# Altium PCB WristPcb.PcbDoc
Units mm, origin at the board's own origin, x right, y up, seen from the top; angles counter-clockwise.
Board outline 152.4 x 101.6 mm, 2 copper layers (Top Layer, Bottom Layer); 4 components, 45 nets, 73 pads, 2 vias.
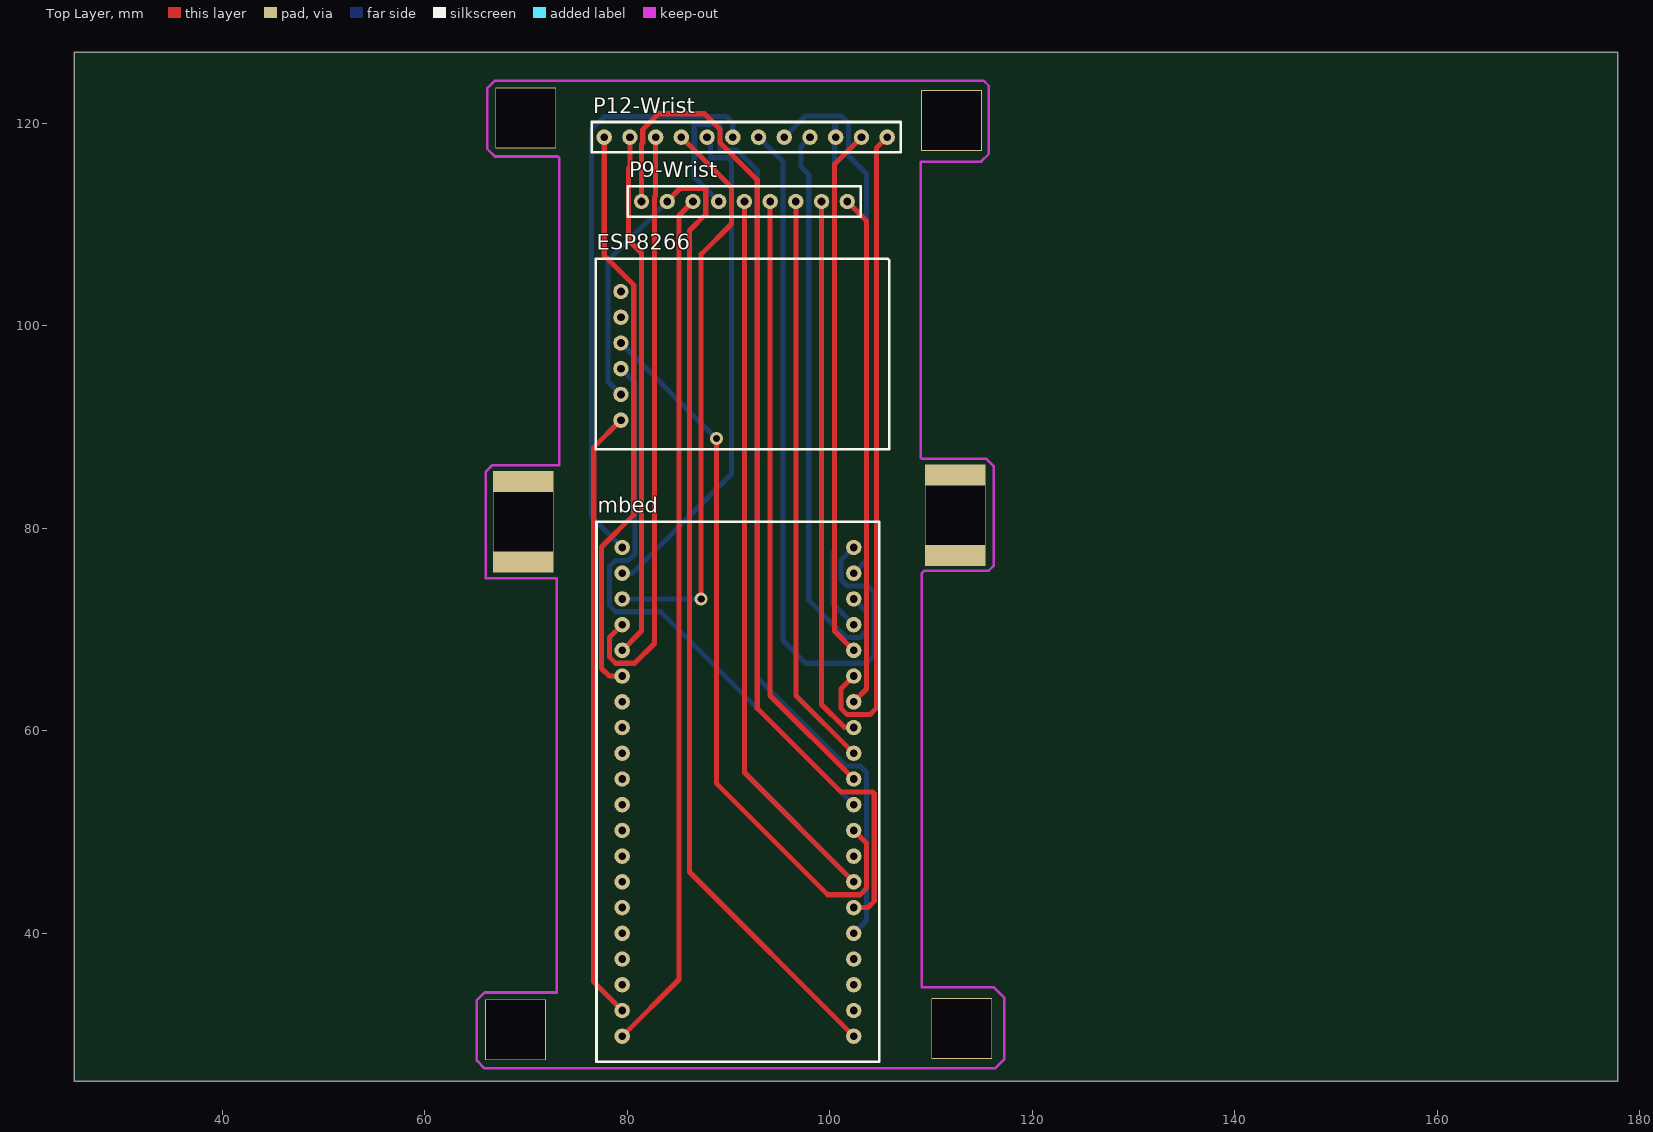
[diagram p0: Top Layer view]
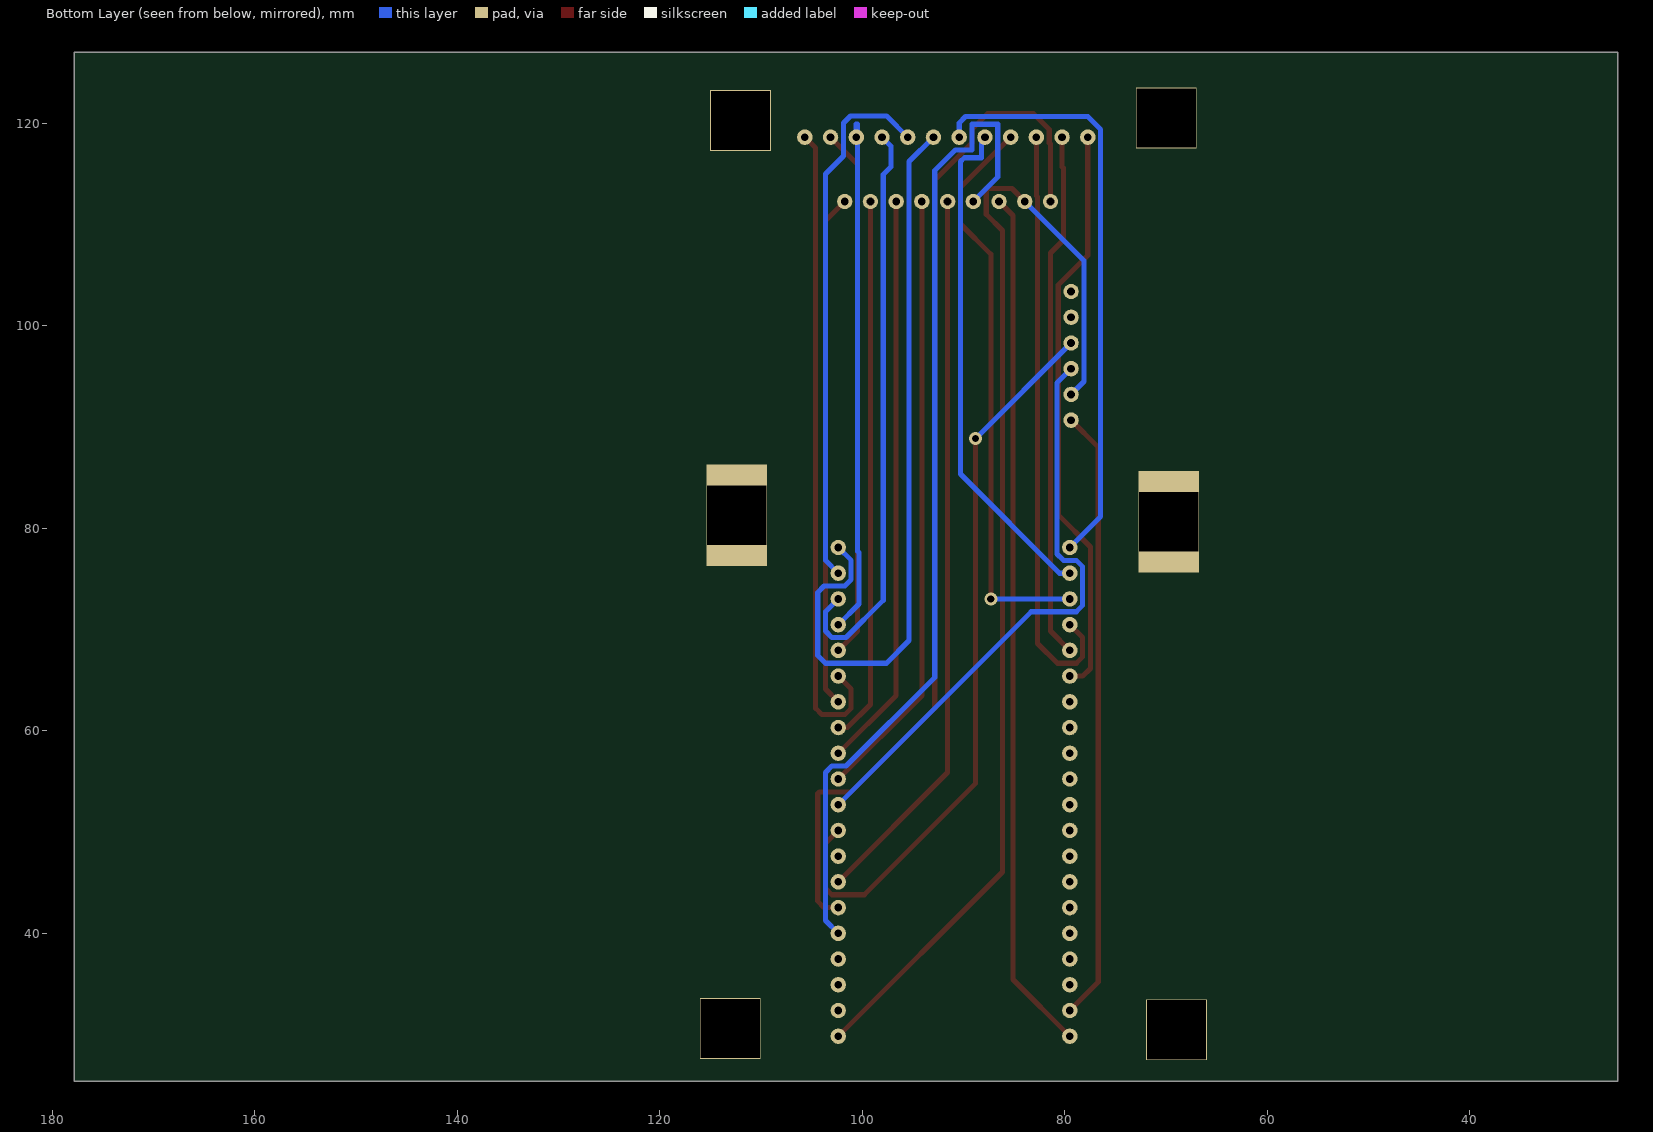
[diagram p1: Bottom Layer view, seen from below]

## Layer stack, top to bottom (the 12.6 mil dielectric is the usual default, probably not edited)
Top Solder: solder mask 0.0102, Solder Resist, Dk 3.5
Top Layer: signal copper 0.0356
Dielectric 1: dielectric 0.32, FR-4, Dk 4.8
Bottom Layer: signal copper 0.0356
Bottom Solder: solder mask 0.0102, Solder Resist, Dk 3.5

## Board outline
25.4,25.4 177.8,25.4 177.8,127 25.4,127

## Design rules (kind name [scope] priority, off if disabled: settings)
Clearance [All] p1: gap=0.254 ignorepadtopadclearanceinfootprint=FALSE except(0: Arc-Hole Track-Hole SMDPad-Hole THPad-Hole Via-Hole Fill-Hole Poly-Hole Region-Hole Text-Hole)
PolygonConnect [All] p1: connectstyle=Relief reliefconductorwidth=0.254 reliefentries=4 polygonreliefangle="90 Angle" airgapwidth=0.254
RoutingVias [All] p1: holewidth=0.711 width=1.27 viastyle="Through Hole" minholewidth=0.711 minwidth=1.27 maxholewidth=0.711 maxwidth=1.27
SolderMaskExpansion [All] p1: expansion=0.102 istentingtop=FALSE
Width [All] p1: maxlimit=0.508 minlimit=0.508 preferedwidth=0.508 minimp=50.000000 maximp=50.000000 favimp=50.000000
30 further rules are at their usual default settings.

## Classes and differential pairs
component class Wrist: ESP8266 P9-Wrist

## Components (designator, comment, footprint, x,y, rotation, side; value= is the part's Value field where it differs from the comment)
ESP8266 "ESP8266" ESP8266 79.375,98.298 r0 top
mbed "mbed" Mbed 102.362,29.845 r180 top
P9-Wrist "9P" 9p 91.567,112.268 r0 top
P12-Wrist "12P" 12P 95.504,118.618 r180 top

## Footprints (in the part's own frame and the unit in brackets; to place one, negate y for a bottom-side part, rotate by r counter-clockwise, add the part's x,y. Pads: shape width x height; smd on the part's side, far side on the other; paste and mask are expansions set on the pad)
9p [mil]
  round 60 hole 30: 1(-400,0) 2(-300,0) 3(-200,0) 4(-100,0) 5(0,0) 6(100,0) 7(200,0) 8(300,0) 9(400,0)
  silkscreen extent -453,-59 453,59
12P [mil]
  round 60 hole 30: 1(-400,0) 2(-300,0) 3(-200,0) 4(-100,0) 5(0,0) 6(100,0) 7(200,0) 8(300,0) 9(400,0) 10(500,0) 11(600,0) 12(700,0)
  silkscreen extent -453,-59 748,59
ESP8266 [mil]
  round 60 hole 30: 1(0,-300) 2(0,-200) 3(0,-100) 4(0,0) 5(0,100) 6(0,200)
  silkscreen extent -98,-413 1043,328
Mbed [mil]
  round 60 hole 30: 1(0,0) 2(0,-100) 3(0,-200) 4(0,-300) 5(0,-400) 6(0,-500) 7(0,-600) 8(0,-700) 9(0,-800) 10(0,-900) 11(0,-1000) 12(0,-1100) 13(0,-1200) 14(0,-1300) 15(0,-1400) 16(0,-1500) 17(0,-1600) 18(0,-1700) 19(0,-1800) 20(0,-1900) 21(900,-1900) 22(900,-1800) 23(900,-1700) 24(900,-1600) 25(900,-1500) 26(900,-1400) 27(900,-1300) 28(900,-1200) 29(900,-1100) 30(900,-1000) 31(900,-900) 32(900,-800) 33(900,-700) 34(900,-600) 35(900,-500) 36(900,-400) 37(900,-300) 38(900,-200) 39(900,-100) 40(900,0)
  silkscreen extent -100,-2000 1000,100

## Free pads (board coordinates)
  rect 6x6 hole 5.8 square: 2(68.961,30.48) 2(69.977,120.523) 2(112.014,120.269) 2(113.03,30.607)
  rect 6x10 hole 5.8 square: 2(69.723,80.645) 2(112.395,81.28)

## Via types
v1: diameter 1.27, hole 0.711, Top Layer to Bottom Layer, 2 vias

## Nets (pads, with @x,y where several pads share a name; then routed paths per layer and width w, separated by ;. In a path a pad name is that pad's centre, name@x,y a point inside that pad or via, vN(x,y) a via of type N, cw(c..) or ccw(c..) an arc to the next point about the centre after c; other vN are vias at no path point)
1: mbed.6 P9-Wrist.1 | length 102.7
  Top Layer w0.508: P9-Wrist.1 81.407,117.932 81.534,118.059 81.534,119.38 83.083,120.929 87.63,120.929 89.154,119.405 89.154,118.059 92.837,114.376 92.837,62.23 101.092,53.975 104.216,53.975 104.394,53.797 104.394,43.18 103.759,42.545 mbed.6
2: ESP8266.2 mbed.1 P9-Wrist.2 | length 117.4
  Top Layer w0.508: P9-Wrist.2 85.217,113.538 87.757,113.538 87.757,110.998 86.157,109.398 86.157,46.05 mbed.1
  Bottom Layer w0.508: ESP8266.2 78.105,94.488 78.105,106.426 P9-Wrist.2
3: mbed.40 P9-Wrist.3 | length 85.3
  Top Layer w0.508: mbed.40 85.115,35.458 85.115,110.896 P9-Wrist.3
4: mbed.5 P9-Wrist.4 | length 99.4
  Bottom Layer w0.508: P9-Wrist.4 86.614,114.681 86.614,119.888 89.154,119.888 89.154,117.348 90.805,117.348 92.837,115.316 92.837,65.278 101.6,56.515 102.997,56.515 103.632,55.88 103.632,41.275 mbed.5
5: mbed.7 P9-Wrist.5 | length 71.7
  Top Layer w0.508: P9-Wrist.5 91.567,55.88 mbed.7
9p1: mbed.11 P9-Wrist.6 | length 60.4
  Top Layer w0.508: P9-Wrist.6 94.107,63.5 mbed.11
9p2: mbed.12 P9-Wrist.7 | length 56.9
  Top Layer w0.508: P9-Wrist.7 96.647,63.5 mbed.12
9p3: mbed.13 P9-Wrist.8 | length 53.8
  Top Layer w0.508: P9-Wrist.8 99.187,62.611 101.473,60.325 mbed.13
9p4: mbed.14 P9-Wrist.9 | length 50.7
  Top Layer w0.508: P9-Wrist.9 103.632,110.363 103.632,64.135 mbed.14
12p1: mbed.15 P12-Wrist.1 | length 64.6
  Top Layer w0.508: mbed.15 101.092,64.135 101.092,62.23 101.727,61.595 103.962,61.595 104.597,62.23 104.597,117.551 P12-Wrist.1
12p2: mbed.16 P12-Wrist.2 | length 52.6
  Top Layer w0.508: mbed.16 100.457,69.85 100.457,115.951 P12-Wrist.2
12p3: mbed.17 P12-Wrist.3 | length 51.8
  Bottom Layer w0.508: P12-Wrist.3 100.584,119.929 100.457,119.929 100.457,77.724 100.33,77.597 100.33,72.517 mbed.17
12p4: mbed.18 P12-Wrist.4 | length 57.6
  Bottom Layer w0.508: P12-Wrist.4 97.155,117.729 97.155,115.697 97.917,114.935 97.917,72.898 101.6,69.215 102.997,69.215 103.632,69.85 103.632,71.755 mbed.18
12p5: mbed.19 P12-Wrist.5 | length 53.2
  Bottom Layer w0.508: P12-Wrist.5 97.587,120.701 101.168,120.701 101.854,120.015 101.854,116.764 103.632,114.986 103.632,76.835 mbed.19
12p6: mbed.20 P12-Wrist.6 | length 74.7
  Bottom Layer w0.508: P12-Wrist.6 95.377,116.205 95.377,68.91 97.612,66.675 103.632,66.675 104.394,67.437 104.394,73.66 103.759,74.295 101.727,74.295 101.092,74.93 101.092,76.835 mbed.20
12p7: mbed.21 P12-Wrist.7 | length 58.7
  Bottom Layer w0.508: mbed.21 76.454,81.153 76.454,119.38 77.724,120.65 89.789,120.65 90.424,120.015 P12-Wrist.7
12p8: mbed.22 P12-Wrist.8 | length 50.1
  Bottom Layer w0.508: mbed.22 80.513,75.565 90.297,85.349 90.297,116.205 89.916,116.586 88.221,116.586 88.221,118.281 P12-Wrist.8
12p9: mbed.23 P12-Wrist.9 | length 56.7
  Top Layer w0.508: P12-Wrist.9 90.297,113.665 90.297,110.058 87.3,107.061 v1(87.3,73.025)
  Bottom Layer w0.508: mbed.23 v1(87.3,73.025)
12p10: mbed.24 P12-Wrist.10 | length 59.3
  Top Layer w0.508: mbed.24 78.232,69.215 78.232,67.31 78.867,66.675 80.721,66.675 82.677,68.631 82.677,112.7 82.804,112.827 P12-Wrist.10
12p11: mbed.25 P12-Wrist.11 | length 52
  Top Layer w0.508: mbed.25 81.407,69.85 81.407,107.188 80.137,108.458 80.137,115.57 80.264,115.697 P12-Wrist.11
12p12: mbed.26 P12-Wrist.12 | length 57.3
  Top Layer w0.508: P12-Wrist.12 77.724,106.934 80.645,104.013 80.645,81.331 77.47,78.156 77.47,66.167 78.232,65.405 mbed.26
esp1: ESP8266.1 mbed.39 | length 60.6
  Top Layer w0.508: ESP8266.1 76.69,87.993 76.69,35.197 mbed.39
esp3: ESP8266.3 mbed.10 | length 58
  Bottom Layer w0.508: ESP8266.3 80.772,94.361 80.772,77.47 80.137,76.835 78.867,76.835 78.232,76.2 78.232,72.39 78.867,71.755 83.312,71.755 mbed.10
esp4: ESP8266.4 mbed.9 | length 73.3
  Top Layer w0.508: v1(88.798,88.875) 88.798,54.813 99.797,43.815 102.997,43.815 103.632,44.45 103.632,48.895 mbed.9
  Bottom Layer w0.508: ESP8266.4 v1(88.798,88.875)
Netimu_1: 
Netimu_2: 
Netimu_3: 
Netimu_4: 
Netimu_6: 
Netimu_7: 
NetP1_6: 
NetP1_7: 
NetP1_8: 
NetP2_6: 
NetP2_7: 
NetP2_8: 
NetP3_6: 
NetP3_7: 
NetP3_8: 
NetP4_6: 
NetP4_7: 
NetP4_8: 
NetP5_6: 
NetP5_7: 
NetP5_8: 
pads on no net: ESP8266.5 ESP8266.6 mbed.2 mbed.3 mbed.4 mbed.8 mbed.27 mbed.28 mbed.29 mbed.30 mbed.31 mbed.32 mbed.33 mbed.34 mbed.35 mbed.36 mbed.37 mbed.38

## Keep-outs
Top Layer:
  lines w0.254: 73.152,124.206 114.935,124.206 115.189,124.206 115.697,123.698 115.697,116.967 114.935,116.205 108.966,116.205 108.966,115.189 108.966,86.995 109.093,86.868 115.443,86.868 116.205,86.106 116.205,76.327 115.697,75.819 115.443,75.819 114.427,75.819 109.347,75.819 109.093,75.565 109.093,34.671 116.205,34.671 117.221,33.655 117.221,27.559 116.332,26.67 115.189,26.67 65.913,26.67 65.151,27.432 65.151,33.401 65.913,34.163 73.025,34.163 73.025,75.057 66.04,75.057 66.04,85.598 66.548,86.106 66.675,86.233 73.279,86.233 73.279,116.586 73.152,116.713 66.929,116.713 66.167,117.475 66.167,123.444 66.929,124.206 73.406,124.206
